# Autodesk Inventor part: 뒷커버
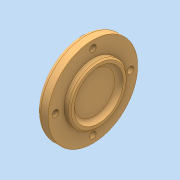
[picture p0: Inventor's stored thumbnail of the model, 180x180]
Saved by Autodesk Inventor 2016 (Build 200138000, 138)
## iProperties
Created: 2024-09
Part Number: 뒷커버
Material: 일반
Document SubType Name: Modeling
Designer: pc-7
Density: 1 g/cm^3
Appearance: 기본값
Author: jhkim
Sending System: Autodesk Inventor 2025
Preprocessor: ST-DEVELOPER v20
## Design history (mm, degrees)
node "뒷커버1"
node "솔리드2"
node "솔리드1"
